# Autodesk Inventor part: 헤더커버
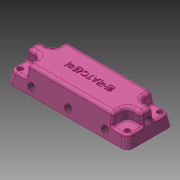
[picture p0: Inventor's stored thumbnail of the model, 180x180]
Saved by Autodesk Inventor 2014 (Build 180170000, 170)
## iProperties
Created: 2015-11
Part Number: 헤더커버
Material: 알루미늄 6061
Document SubType Name: Modeling
Designer: mduedu
Density: 2.71 g/cm^3
Mass: 159.45 g
Surface Area: 159.64 cm^2
Volume: 58.8375 cm^3
Appearance: 분홍색
Author: mduedu
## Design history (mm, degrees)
sketch "스케치1"
  geometry: L1 (52.5, 20)-(-52.5, 20); L2 (-52.5, 20)-(-52.5, -20); L3 (-52.5, -20)-(52.5, -20); L4 (52.5, -20)-(52.5, 20); L5 (52.5, 20)-(-52.5, -20); L6 (-52.5, 20)-(52.5, -20); 1 further point
  constraints: 12 end point, 2 midpoint, 2 parallel, 1 horizontal, 1 perpendicular
  dimensions: "d0" = 105 distance of L3.end L2.end; "d1" = 40 distance of L2.end L1.end
extrude "돌출1" new body sketch "스케치1" distance "d2" = 22; taper "d3" = -10 deg
sketch "스케치2"
  geometry: L1 (-48.621, -16.121)-(-48.621, 16.121) reference; L2 (-48.621, 16.121)-(48.621, 16.121) reference; L3 (48.621, 16.121)-(48.621, -16.121) reference; L4 (48.621, -16.121)-(-48.621, -16.121) reference; L5 (-37.5, 20)-(-37.5, 5); L6 (-37.5, 5)-(-52.5, 5); L7 (37.5, 20)-(37.5, 5); L8 (37.5, 5)-(52.5, 5); L9 (37.5, -20)-(37.5, -5); L10 (37.5, -5)-(52.5, -5); L11 (-37.5, -20)-(-37.5, -5); L12 (-37.5, -5)-(-52.5, -5); L13 (52.5, 20)-(-52.5, 20) reference; L14 (-52.5, -20)-(52.5, -20) reference; L15 (-52.5, 20)-(-52.5, -20) reference; L16 (52.5, -20)-(52.5, 20) reference; 5 further points
  constraints: 16 end point, 12 point on line, 7 equal length, 4 horizontal, 3 vertical
  dimensions: "d91" = 15 distance between parallel lines of L5 L15
extrude "돌출2" cut sketch "스케치2" distance "d6" = 12; taper "d7" = 0 deg
fillet "모깎기1" dims "d8" = 5
fillet "모깎기2" dims "d9" = 1
fillet "모깎기3" dims "d10" = 5
fillet "모깎기4" dims "d11" = 2
fillet "모깎기5" dims "d12" = 3
sketch "스케치3"
  geometry: L1 (-45.5, -13)-(45.5, -13); L2 (45.5, -13)-(45.5, 13); L3 (45.5, 13)-(-45.5, 13); L4 (-45.5, 13)-(-45.5, -13); L5 (-45.5, -13)-(45.5, 13); L6 (45.5, -13)-(-45.5, 13); L7 (47.576, 20)-(-47.576, 20) reference; L8 (52.5, -15.076)-(52.5, 15.076) reference; 5 further points
  constraints: 12 end point, 4 coincident, 2 midpoint, 2 parallel, 1 horizontal, 1 perpendicular
  dimensions: "d13" = 7 distance between parallel lines of L3 L7 (= d14); "d14" = 7 distance between parallel lines of L2 L8
hole "구멍1" sketch "스케치3" at (-45.5, 13), (45.5, 13), (45.5, -13), (-45.5, -13) diameter "d15" = 4.5; stored, may be unused: countersink angle "d19" = 90 deg, drill point angle "d21" = 118 deg; dims "d16" = 6, "d17" = 4, "d18" = 2, "d20" = 8
sketch "스케치4"
  geometry: L1 (47.576, -20)-(-47.576, -20) reference; L2 (52.5, 15.076)-(52.5, -15.076) reference; L3 (-47.576, 20)-(47.576, 20) reference; L4 (-52.5, -15.076)-(-52.5, 15.076) reference; L5 (-52.5, 0)-(52.5, 0); C1 r 12.25 at (0, 0); C2 r 2.25 at (45.5, 13) reference; C3 r 2.25 at (-45.5, -13) reference; C4 r 2.25 at (45.5, -13) reference; C5 r 2.25 at (-45.5, 13) reference; C6 r 12.25 at (-32, 0); C7 r 12.25 at (32, 0); 5 further points
  constraints: 3 centre point, 2 end point, 2 midpoint, 2 point on line, 1 coincident, 4 other
  dimensions: "d22" = 24.5 diameter of C1; "d23" = 24.5 diameter of C7 (= d22); "d24" = 24.5 diameter of C6 (= d22); "d25" = 32 distance of point (0, 0) C6.centre; "d26" = 32 distance of C7.centre point (0, 0) (= d25)
extrude "돌출3" cut sketch "스케치4" distance "d27" = 9; taper "d28" = 0 deg
fillet "모깎기6" dims "d29" = 5
sketch "스케치5"
  geometry: L1 (-50.031, 14)-(-43.051, 12.769); L2 (-38.312, 10.033)-(-35.04, 6.134); L3 (-49.089, 19.347)-(-50.499, 11.347) reference; L4 (-47.576, 0)-(-52.5, 0) reference; L5 (0, 0)-(0, 22); L6 (50.031, 14)-(43.051, 12.769); L7 (38.312, 10.033)-(35.04, 6.134); A1 r 8 centre (-44.44, 4.891) between (-38.312, 10.033) and (-43.051, 12.769); A2 r 8 centre (44.44, 4.891) between (43.051, 12.769) and (38.312, 10.033); 4 further points; 1 other entity
  constraints: 10 end point, 5 symmetric about line, 4 point on circle, 3 point on line, 2 centre point, 2 tangent, 1 perpendicular, 3 other
  dimensions: "d30" = 10 distance of L1.start point (-40.183, 12.264); "d32" = 140 deg angle of L2 L1; "d35" = 8 radius of A1; "d96" = 14 vertical distance of L1.start L4.end
sketch "스케치6"
  geometry: L1 (22, -2)-(22, 2) reference; L2 (11.347, -17.999)-(19.347, -16.589) reference; L3 (10.033, -5.812)-(5.684, -2.162); L4 (0, -20)-(0, -15.076) reference; L5 (12.769, -10.551)-(14, -17.531); A1 r 8 centre (4.891, -11.94) between (12.769, -10.551) and (10.033, -5.812); 2 further points
  constraints: 4 end point, 3 point on line, 2 point on circle, 2 tangent, 1 centre point, 1 perpendicular
  dimensions: "d36" = 10 distance of L5.end point (12.264, -7.683); "d40" = 8 radius of A1; "d94" = 140 deg angle of L3 L5; "d97" = 14 horizontal distance of L5.end L4.start
node "작업점1"
node "작업점2"
node "작업점3"
hole "구멍2" diameter "d43" = 5.944; stored, may be unused: countersink angle "d49" = 90 deg, drill point angle "d51" = 0 deg; dims "d41" = 10, "d42" = 10, "d44" = 6.886, "d45" = 0.62479, "d46" = 5.959, "d47" = 4, "d48" = 2, "d50" = 6.9
hole "구멍3" diameter "d54" = 5.944; stored, may be unused: countersink angle "d60" = 90 deg, drill point angle "d62" = 0 deg; dims "d55" = 6.886, "d56" = 0.62479, "d57" = 5.959, "d58" = 4, "d59" = 2, "d61" = 6.9, "d92" = 10, "d93" = 10
hole "구멍4" diameter "d65" = 5.944; stored, may be unused: countersink angle "d71" = 90 deg, drill point angle "d73" = 0 deg; dims "d63" = 10, "d64" = 10, "d66" = 6.886, "d67" = 0.62479, "d68" = 5.959, "d69" = 4, "d70" = 2, "d72" = 6.9
sketch "스케치7"
  geometry: C1 r 2.972 at (15.076, 14.216) reference; 1 further point
sketch "스케치8"
  geometry: C1 r 2.972 at (15.076, 14.216) reference; 1 further point
sketch "스케치9"
  geometry: C1 r 2.972 at (47.576, 14.216) reference; 1 further point
feature "스윕1" dims "d74" = 0
feature "스윕2" dims "d75" = 0
feature "스윕3" dims "d76" = 0
sketch "스케치10"
  geometry: L1 (15.576, 9)-(15.576, 0); L2 (47.576, 9)-(47.576, 3.473); L3 (79.576, 9)-(79.576, 0); 8 further points; 3 other entities
  constraints: 6 end point, 3 point on line, 2 horizontal alignment, 2 vertical, 2 vertical alignment, 1 parallel, 6 other
  dimensions: "d77" = 6 dimension on point (15.576, 6)
hole "구멍5" sketch "스케치10" diameter "d78" = 5.944; stored, may be unused: countersink angle "d84" = 90 deg, drill point angle "d86" = 0 deg; dims "d79" = 6.886, "d80" = 0.62479, "d81" = 5.959, "d82" = 4, "d83" = 2, "d85" = 6.9
sketch "스케치11"
  geometry: C1 r 2.972 at (0, 0) reference; C2 r 2.972 at (32, 0) reference; C3 r 2.972 at (64, 0) reference; 1 further point
extrude "돌출4" cut sketch "스케치11" distance "d87" = 8; taper "d88" = 0 deg
sketch "스케치12"
  geometry: 2 further points
  constraints: 1 coincident, 1 other
feature "엠보싱1" sketch "스케치12" dims "d0" = 105, "d1" = 40, "d9" = 1, "d89" = 0.5, "d90" = 0
node "솔리드1"
node "투영된 루프1"
node "절단 모서리 투영1"
